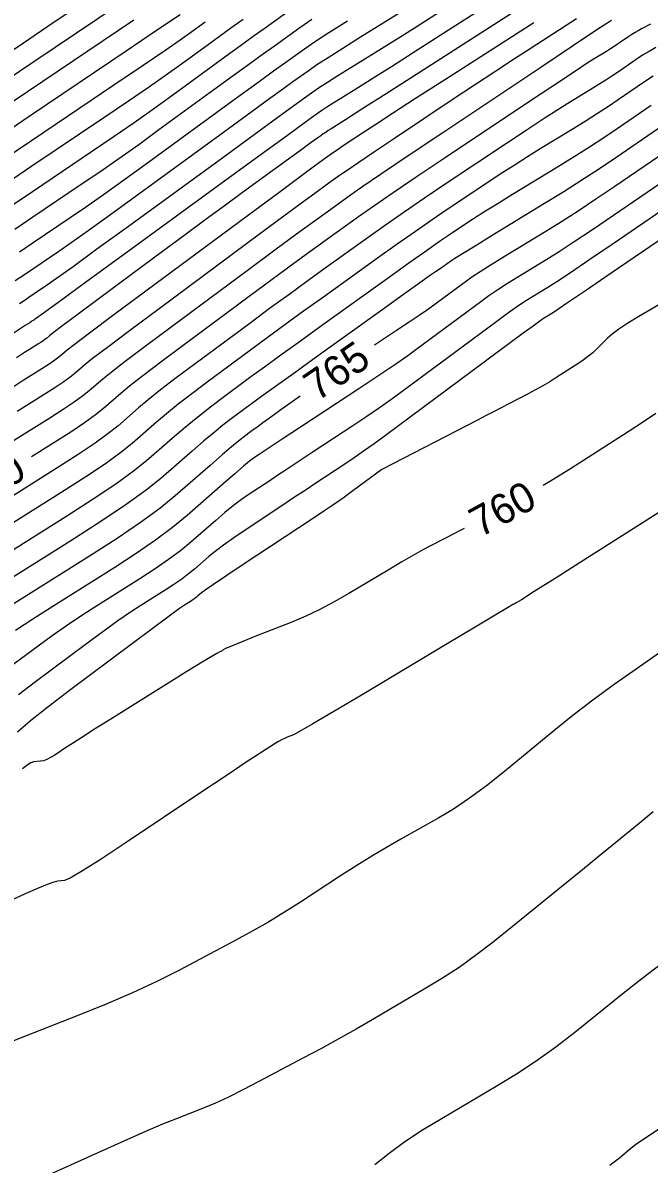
# Model space of a CAD drawing. Extents: x 2079879 to 2092887, y 778083 to 784051.
# Drawn here: x 2084585.7 to 2084644.1, y 781146.9 to 781253.2 of the extents above; entities that cross this region are included whole.
import ezdxf

# ---------------------------------------------------------------- set-up
doc = ezdxf.new("R2010")
doc.units = 0
doc.layers.add('DT_X_Contour_Major', color=7, linetype='Continuous')
doc.layers.add('DT_X_Contour_Minor', color=7, linetype='Continuous')

msp = doc.modelspace()

# ---------------------------------------------------------------- linework, layer by layer
at = {"layer": 'DT_X_Contour_Major'}
for points in [[(2084632, 781256.8), (2084624.61, 781252.06), (2084622.09, 781250.45), (2084620.06, 781249.15), (2084618.52, 781248.17), (2084617.48, 781247.52), (2084615.35, 781246.2), (2084614.62, 781245.75), (2084614.03, 781245.37), (2084613.57, 781245.08), (2084613.25, 781244.86), (2084612.59, 781244.39), (2084611.91, 781243.89), (2084610.35, 781242.75), (2084607.91, 781240.98), (2084604.6, 781238.56), (2084594.6, 781231.28), (2084591.31, 781228.88), (2084588.94, 781227.15), (2084587.49, 781226.1), (2084586.96, 781225.71), (2084586.77, 781225.59), (2084586.7, 781225.54), (2084586.64, 781225.5), (2084586.57, 781225.45), (2084586.51, 781225.41), (2084586.34, 781225.29), (2084585.92, 781225.02), (2084584.8, 781224.27)], [(2084594.67, 781254.96), (2084586.71, 781249.59), (2084584.05, 781247.8), (2084582.03, 781246.44), (2084580.66, 781245.51), (2084579.93, 781245.02), (2084578.85, 781244.3), (2084578.48, 781244.04), (2084578.16, 781243.83), (2084577.89, 781243.65), (2084577.68, 781243.5), (2084577.2, 781243.17), (2084576.64, 781242.79), (2084575.32, 781241.88), (2084573.25, 781240.45), (2084570.42, 781238.5), (2084561.86, 781232.61), (2084561.21, 781232.17)], [(2084611.07, 781254.75), (2084608.27, 781252.74), (2084607.17, 781251.95), (2084605.97, 781251.08), (2084604.66, 781250.13), (2084603.24, 781249.1), (2084599.33, 781246.24), (2084597.78, 781245.13), (2084596.07, 781243.93), (2084594.21, 781242.64), (2084592.19, 781241.27), (2084586.58, 781237.49), (2084584.51, 781236.09), (2084582.5, 781234.72), (2084580.56, 781233.39), (2084578.67, 781232.1), (2084573.73, 781228.7), (2084571.94, 781227.46), (2084570.26, 781226.32), (2084568.69, 781225.27), (2084568.44, 781225.1)], [(2084644.2, 781253.11), (2084643.37, 781252.67), (2084643.07, 781252.5), (2084642.77, 781252.33), (2084642.47, 781252.14), (2084642.18, 781251.95), (2084641.42, 781251.43), (2084641.13, 781251.24), (2084640.81, 781251.03), (2084640.47, 781250.81), (2084640.1, 781250.58), (2084639.1, 781249.97), (2084638.41, 781249.53), (2084637.11, 781248.68), (2084635.19, 781247.41), (2084632.66, 781245.72), (2084625.08, 781240.67), (2084622.44, 781238.9), (2084620.21, 781237.4), (2084618.4, 781236.15), (2084616.99, 781235.16), (2084613.79, 781232.86), (2084612.45, 781231.89), (2084610.84, 781230.72), (2084608.95, 781229.32), (2084606.78, 781227.72), (2084600.63, 781223.17), (2084598.54, 781221.61), (2084596.87, 781220.34), (2084595.63, 781219.37), (2084594.82, 781218.7), (2084593.21, 781217.3), (2084592.47, 781216.7), (2084591.45, 781215.97), (2084590.15, 781215.1), (2084588.57, 781214.09), (2084586.49, 781212.78)], [(2084645.66, 781241.25), (2084640.87, 781237.98), (2084639.12, 781236.79), (2084637.46, 781235.7), (2084635.9, 781234.7), (2084634.44, 781233.79), (2084630.65, 781231.48), (2084629.36, 781230.68), (2084628.33, 781230.03), (2084627.56, 781229.53), (2084627.04, 781229.17), (2084623.76, 781226.73), (2084623.32, 781226.42), (2084622.64, 781225.96), (2084621.71, 781225.34), (2084620.54, 781224.56), (2084618.47, 781223.19)], [(2084611.54, 781218.44), (2084609.75, 781217.16), (2084608.82, 781216.49), (2084608.07, 781215.95), (2084607.49, 781215.53), (2084607.08, 781215.23), (2084606.23, 781214.6), (2084605.8, 781214.26), (2084605.15, 781213.71), (2084604.26, 781212.96), (2084603.15, 781211.99), (2084599.88, 781209.14), (2084598.46, 781207.98), (2084596.66, 781206.66), (2084594.47, 781205.18), (2084591.9, 781203.53), (2084584.53, 781198.9)], [(2084644.7, 781216.84), (2084643.37, 781215.92), (2084641.68, 781214.83), (2084636.74, 781211.68), (2084634.99, 781210.58), (2084634.21, 781210.11)], [(2084626.83, 781206.1), (2084626.53, 781205.95), (2084625.8, 781205.57), (2084625.17, 781205.25), (2084623.65, 781204.47), (2084622.98, 781204.11), (2084622.11, 781203.62), (2084621.04, 781203), (2084619.76, 781202.24), (2084616.09, 781200.05), (2084614.73, 781199.27), (2084613.39, 781198.56), (2084612.07, 781197.94), (2084610.77, 781197.39), (2084607.33, 781196.03), (2084606.19, 781195.58), (2084605.35, 781195.24), (2084604.82, 781195.02), (2084604.59, 781194.92), (2084604.38, 781194.79), (2084604.26, 781194.72), (2084604.06, 781194.61), (2084603.79, 781194.45), (2084602.4, 781193.64), (2084601.85, 781193.31), (2084600.98, 781192.78), (2084599.8, 781192.05), (2084598.3, 781191.11), (2084593.88, 781188.34), (2084592.38, 781187.4), (2084591.19, 781186.64), (2084590.32, 781186.08), (2084589.75, 781185.72), (2084588.66, 781184.99), (2084588.27, 781184.75), (2084587.92, 781184.57), (2084587.62, 781184.46), (2084587.35, 781184.41), (2084586.69, 781184.37), (2084586.42, 781184.28), (2084586.08, 781184.06), (2084585.67, 781183.7)], [(2084661.61, 781160.96), (2084659.04, 781159.23), (2084656.15, 781157.33), (2084648.5, 781152.39), (2084645.96, 781150.74), (2084644.06, 781149.49), (2084642.81, 781148.65), (2084642.22, 781148.21), (2084641.49, 781147.59), (2084641.19, 781147.34), (2084640.83, 781147.05), (2084640.42, 781146.73)]]:
    msp.add_lwpolyline(points, dxfattribs=at)
at = {"layer": 'DT_X_Contour_Minor'}
for points in [[(2084594.68, 781257.37), (2084588.03, 781252.89), (2084585.74, 781251.34), (2084583.84, 781250.06)], [(2084622.06, 781254.92), (2084617.18, 781251.9), (2084615.51, 781250.85), (2084614.15, 781249.99), (2084613.11, 781249.31), (2084612.38, 781248.81), (2084610.87, 781247.73), (2084610.01, 781247.11), (2084608.6, 781246.08), (2084606.61, 781244.64), (2084604.06, 781242.78), (2084596.49, 781237.26), (2084593.9, 781235.38), (2084591.79, 781233.86), (2084590.18, 781232.72), (2084589.05, 781231.94), (2084586.7, 781230.35), (2084585.83, 781229.76), (2084584.98, 781229.19)], [(2084631.69, 781254.4), (2084622.58, 781248.55), (2084619.56, 781246.62), (2084617.31, 781245.18), (2084615.86, 781244.25), (2084615.18, 781243.82), (2084614.43, 781243.36), (2084614.17, 781243.2), (2084613.96, 781243.06), (2084613.8, 781242.96), (2084613.69, 781242.88), (2084613.46, 781242.72), (2084613.19, 781242.52), (2084612.57, 781242.07), (2084611.58, 781241.35), (2084610.24, 781240.37), (2084606.18, 781237.41), (2084604.57, 781236.23), (2084602.79, 781234.93), (2084600.83, 781233.48), (2084598.7, 781231.91), (2084592.79, 781227.53), (2084590.84, 781226.08), (2084589.42, 781225.02), (2084588.52, 781224.35), (2084588.16, 781224.07), (2084587.88, 781223.83), (2084587.75, 781223.72), (2084587.58, 781223.6), (2084587.36, 781223.45), (2084587.09, 781223.28), (2084586.3, 781222.78), (2084585.85, 781222.5), (2084585.09, 781222.01)], [(2084624.63, 781254.28), (2084622.81, 781253.12), (2084621.19, 781252.1), (2084619.77, 781251.22), (2084616.26, 781249.05), (2084615.06, 781248.3), (2084614.09, 781247.68), (2084613.34, 781247.2), (2084612.82, 781246.84), (2084611.73, 781246.06), (2084610.96, 781245.5), (2084609.47, 781244.42), (2084607.26, 781242.81), (2084604.33, 781240.67), (2084595.54, 781234.27), (2084592.6, 781232.13), (2084590.37, 781230.51), (2084588.83, 781229.41), (2084588, 781228.82), (2084586.73, 781227.97), (2084586.26, 781227.65), (2084585.81, 781227.34), (2084585.37, 781227.04)], [(2084600.35, 781253.99), (2084598.24, 781252.57), (2084595.32, 781250.6), (2084586.47, 781244.63), (2084583.2, 781242.42)], [(2084602.7, 781253.31), (2084601.22, 781252.23), (2084600.37, 781251.63), (2084598.93, 781250.64), (2084596.9, 781249.26), (2084594.28, 781247.49), (2084586.51, 781242.25), (2084583.64, 781240.31)], [(2084606.23, 781253.56), (2084605.09, 781252.74), (2084604.01, 781251.96), (2084602.97, 781251.2), (2084600.27, 781249.24), (2084599.07, 781248.38), (2084597.5, 781247.28), (2084595.55, 781245.95), (2084593.23, 781244.38), (2084586.54, 781239.87), (2084584.07, 781238.2)], [(2084596.05, 781253.49), (2084586.12, 781246.8), (2084584.15, 781245.47)], [(2084640.57, 781253.47), (2084639.21, 781252.57), (2084637.02, 781251.11), (2084633.98, 781249.08), (2084624.74, 781242.92), (2084621.6, 781240.83), (2084619.12, 781239.15), (2084617.29, 781237.91), (2084616.11, 781237.08), (2084613.83, 781235.45), (2084612.75, 781234.66), (2084611.2, 781233.53), (2084609.19, 781232.05), (2084606.72, 781230.22), (2084599.51, 781224.88), (2084597.09, 781223.08), (2084595.22, 781221.67), (2084593.91, 781220.66), (2084593.15, 781220.04), (2084591.88, 781218.93), (2084591.29, 781218.46), (2084590.48, 781217.88), (2084589.45, 781217.19), (2084588.2, 781216.39), (2084584.57, 781214.11)], [(2084633.33, 781253.25), (2084625.1, 781247.97), (2084622.31, 781246.18), (2084620.14, 781244.78), (2084618.59, 781243.77), (2084617.64, 781243.15), (2084615.93, 781242.01), (2084615.35, 781241.62), (2084614.89, 781241.31), (2084614.55, 781241.08), (2084614.33, 781240.93), (2084613.91, 781240.63), (2084613.34, 781240.21), (2084611.93, 781239.16), (2084609.68, 781237.5), (2084606.6, 781235.22), (2084597.27, 781228.31), (2084594.18, 781226.01), (2084591.91, 781224.32), (2084590.46, 781223.22), (2084589.82, 781222.72), (2084589.21, 781222.19), (2084588.93, 781221.97), (2084588.55, 781221.69), (2084588.05, 781221.36), (2084587.46, 781220.98), (2084585.72, 781219.89), (2084584.87, 781219.35)], [(2084612.64, 781253.55), (2084611.51, 781252.77), (2084609.14, 781251.07), (2084608.12, 781250.34), (2084606.84, 781249.41), (2084605.31, 781248.3), (2084603.51, 781246.99), (2084598.38, 781243.25), (2084596.49, 781241.88), (2084594.65, 781240.57), (2084592.87, 781239.33), (2084591.14, 781238.16), (2084586.62, 781235.11), (2084584.95, 781233.98)], [(2084637.32, 781253.6), (2084633.09, 781250.89), (2084631.44, 781249.82), (2084629.68, 781248.68), (2084627.8, 781247.44), (2084625.81, 781246.11), (2084620.33, 781242.47), (2084618.48, 781241.22), (2084617, 781240.23), (2084615.92, 781239.49), (2084615.22, 781239.01), (2084613.87, 781238.04), (2084613.04, 781237.43), (2084611.56, 781236.35), (2084609.44, 781234.78), (2084606.66, 781232.72), (2084598.39, 781226.59), (2084595.64, 781224.54), (2084593.57, 781222.99), (2084592.18, 781221.94), (2084591.49, 781221.38), (2084590.55, 781220.56), (2084590.11, 781220.21), (2084589.51, 781219.78), (2084588.75, 781219.27), (2084587.83, 781218.68), (2084585.15, 781217)], [(2084615.95, 781253.4), (2084614.21, 781252.3), (2084612.87, 781251.43), (2084611.94, 781250.79), (2084610, 781249.4), (2084609.07, 781248.72), (2084607.72, 781247.75), (2084605.96, 781246.47), (2084603.78, 781244.88), (2084597.44, 781240.26), (2084595.19, 781238.63), (2084593.22, 781237.22), (2084591.52, 781236.02), (2084590.1, 781235.05), (2084586.66, 781232.73), (2084585.39, 781231.87)], [(2084644.7, 781250.95), (2084644.08, 781250.58), (2084643.47, 781250.21), (2084642.88, 781249.81), (2084641.31, 781248.74), (2084640.7, 781248.33), (2084640.04, 781247.9), (2084639.34, 781247.46), (2084638.59, 781246.99), (2084636.51, 781245.73), (2084635.57, 781245.14), (2084634.3, 781244.31), (2084632.7, 781243.26), (2084630.77, 781241.98), (2084625.17, 781238.25), (2084623.14, 781236.89), (2084621.25, 781235.6), (2084619.5, 781234.38), (2084617.88, 781233.23), (2084613.75, 781230.27), (2084612.16, 781229.12), (2084610.48, 781227.9), (2084608.7, 781226.6), (2084606.84, 781225.22), (2084601.75, 781221.45), (2084599.99, 781220.14), (2084598.53, 781219.02), (2084597.36, 781218.09), (2084596.48, 781217.36), (2084594.55, 781215.66), (2084593.65, 781214.95), (2084592.42, 781214.06), (2084590.85, 781213.01), (2084588.94, 781211.79), (2084583.42, 781208.32)], [(2084644.47, 781248.27), (2084643.57, 781247.67), (2084641.2, 781246.05), (2084640.28, 781245.43), (2084639.28, 781244.78), (2084638.21, 781244.1), (2084637.07, 781243.4), (2084633.93, 781241.48), (2084632.73, 781240.74), (2084631.49, 781239.95), (2084630.2, 781239.12), (2084628.87, 781238.24), (2084625.26, 781235.83), (2084623.84, 781234.87), (2084622.29, 781233.8), (2084620.59, 781232.61), (2084618.77, 781231.31), (2084613.71, 781227.68), (2084611.86, 781226.35), (2084610.11, 781225.08), (2084608.46, 781223.87), (2084606.9, 781222.72), (2084602.87, 781219.74), (2084601.45, 781218.67), (2084600.18, 781217.69), (2084599.08, 781216.81), (2084598.15, 781216.02), (2084595.88, 781214.03), (2084594.83, 781213.19), (2084593.39, 781212.15), (2084591.55, 781210.92), (2084589.32, 781209.5), (2084582.84, 781205.43)], [(2084644.27, 781245.53), (2084641.09, 781243.36), (2084639.85, 781242.53), (2084638.51, 781241.66), (2084637.08, 781240.75), (2084635.55, 781239.8), (2084631.35, 781237.24), (2084629.9, 781236.34), (2084628.68, 781235.59), (2084627.71, 781234.97), (2084626.98, 781234.5), (2084625.36, 781233.42), (2084624.54, 781232.86), (2084623.32, 781232), (2084621.69, 781230.84), (2084619.65, 781229.39), (2084613.67, 781225.09), (2084611.57, 781223.58), (2084609.75, 781222.27), (2084608.21, 781221.15), (2084606.96, 781220.23), (2084603.99, 781218.03), (2084602.9, 781217.2), (2084601.84, 781216.37), (2084600.81, 781215.52), (2084599.82, 781214.67), (2084597.21, 781212.4), (2084596.01, 781211.44), (2084594.35, 781210.25), (2084592.25, 781208.83), (2084589.69, 781207.2), (2084582.26, 781202.54)], [(2084644.96, 781243.39), (2084640.98, 781240.67), (2084639.44, 781239.64), (2084637.82, 781238.58), (2084636.12, 781237.5), (2084634.33, 781236.39), (2084629.46, 781233.41), (2084627.85, 781232.43), (2084626.68, 781231.71), (2084625.96, 781231.27), (2084625.68, 781231.09), (2084625.17, 781230.71), (2084625.11, 781230.67), (2084625, 781230.59), (2084624.86, 781230.5), (2084624.68, 781230.38), (2084624.15, 781230.03), (2084623.69, 781229.71), (2084622.7, 781229.01), (2084621.19, 781227.93), (2084619.16, 781226.47), (2084613.04, 781222.08), (2084610.94, 781220.57), (2084609.24, 781219.35), (2084607.93, 781218.4), (2084607.02, 781217.73), (2084605.11, 781216.32), (2084604.35, 781215.73), (2084603.49, 781215.04), (2084602.53, 781214.24), (2084601.48, 781213.33), (2084598.54, 781210.77), (2084597.19, 781209.68), (2084595.32, 781208.34), (2084592.95, 781206.75), (2084590.06, 781204.9), (2084581.69, 781199.64)], [(2084646.35, 781239.11), (2084640.75, 781235.28), (2084638.79, 781233.95), (2084637.1, 781232.83), (2084635.69, 781231.9), (2084634.54, 781231.18), (2084631.85, 781229.54), (2084630.88, 781228.93), (2084629.98, 781228.35), (2084629.15, 781227.79), (2084628.4, 781227.24), (2084622.34, 781222.75), (2084621.57, 781222.21), (2084620.45, 781221.44), (2084618.96, 781220.43), (2084617.1, 781219.2), (2084611.68, 781215.62), (2084609.88, 781214.43), (2084608.57, 781213.56), (2084607.73, 781213.01), (2084607.38, 781212.78), (2084607.07, 781212.57), (2084606.82, 781212.37), (2084606.27, 781211.91), (2084605.45, 781211.2), (2084604.34, 781210.24), (2084601.01, 781207.33), (2084599.65, 781206.21), (2084598.07, 781205.02), (2084596.27, 781203.78), (2084594.26, 781202.47), (2084588.59, 781198.91), (2084586.62, 781197.67), (2084584.99, 781196.61)], [(2084647.04, 781236.96), (2084640.64, 781232.59), (2084638.47, 781231.11), (2084636.74, 781229.95), (2084635.47, 781229.11), (2084634.64, 781228.58), (2084633.05, 781227.6), (2084632.39, 781227.19), (2084631.62, 781226.67), (2084630.74, 781226.04), (2084629.75, 781225.32), (2084620.92, 781218.77), (2084620, 781218.11), (2084618.95, 781217.37), (2084617.77, 781216.56), (2084616.45, 781215.68), (2084612.75, 781213.24), (2084611.45, 781212.38), (2084610.33, 781211.64), (2084609.38, 781211.01), (2084608.61, 781210.5), (2084606.79, 781209.3), (2084606.09, 781208.81), (2084605.33, 781208.24), (2084604.53, 781207.59), (2084603.68, 781206.86), (2084601.34, 781204.82), (2084600.39, 781204.04), (2084599.28, 781203.21), (2084598.03, 781202.34), (2084596.61, 781201.42), (2084592.64, 781198.93), (2084591.18, 781197.99), (2084589.77, 781197.05), (2084588.41, 781196.11), (2084587.11, 781195.15), (2084583.71, 781192.62)], [(2084647.74, 781234.82), (2084640.53, 781229.9), (2084638.14, 781228.27), (2084636.38, 781227.07), (2084635.25, 781226.31), (2084634.75, 781225.98), (2084634.24, 781225.67), (2084633.9, 781225.44), (2084633.27, 781224.98), (2084632.34, 781224.3), (2084631.11, 781223.4), (2084619.5, 781214.79), (2084618.43, 781214.01), (2084617.46, 781213.31), (2084616.58, 781212.7), (2084615.79, 781212.17), (2084613.82, 781210.86), (2084613.02, 781210.33), (2084612.09, 781209.72), (2084611.03, 781209.02), (2084609.84, 781208.23), (2084606.52, 781206.02), (2084605.36, 781205.24), (2084604.39, 781204.56), (2084603.61, 781203.97), (2084603.02, 781203.49), (2084601.68, 781202.32), (2084601.13, 781201.87), (2084600.5, 781201.4), (2084599.78, 781200.9), (2084598.97, 781200.37), (2084596.69, 781198.94), (2084595.73, 781198.31), (2084594.55, 781197.49), (2084593.14, 781196.48), (2084591.51, 781195.27), (2084586.87, 781191.81), (2084585.29, 781190.6)], [(2084646.09, 781227.61), (2084643.12, 781225.86), (2084642.1, 781225.24), (2084641.27, 781224.7), (2084640.62, 781224.23), (2084640.17, 781223.82), (2084639.22, 781222.85), (2084638.82, 781222.48), (2084638.35, 781222.1), (2084637.81, 781221.7), (2084637.2, 781221.3), (2084635.47, 781220.2), (2084634.82, 781219.79), (2084634.16, 781219.4), (2084633.49, 781219.03), (2084632.81, 781218.66), (2084631, 781217.72), (2084630.3, 781217.36), (2084629.58, 781216.99), (2084628.84, 781216.61), (2084628.08, 781216.21), (2084619.15, 781211.61), (2084616.47, 781209.62), (2084615.95, 781209.24), (2084615.56, 781208.95), (2084615.29, 781208.75), (2084615.14, 781208.65), (2084614.89, 781208.49), (2084614.59, 781208.28), (2084613.85, 781207.79), (2084612.68, 781207.02), (2084606.24, 781202.74), (2084604.63, 781201.68), (2084603.45, 781200.88), (2084602.69, 781200.36), (2084602.35, 781200.11), (2084602.01, 781199.82), (2084601.87, 781199.7), (2084601.71, 781199.58), (2084601.53, 781199.46), (2084601.33, 781199.32), (2084600.75, 781198.96), (2084600.28, 781198.64), (2084599.32, 781197.93), (2084597.86, 781196.85), (2084595.91, 781195.39), (2084590.03, 781191), (2084588.02, 781189.47), (2084586.41, 781188.18), (2084585.2, 781187.12)], [(2084646.16, 781208.36), (2084638, 781203.16), (2084635.31, 781201.46), (2084633.37, 781200.23), (2084632.18, 781199.47), (2084631.75, 781199.2), (2084631.58, 781199.11), (2084631.51, 781199.08), (2084631.46, 781199.05), (2084631.41, 781199.03), (2084631.37, 781199.01), (2084631.28, 781198.96), (2084630.87, 781198.72), (2084629.74, 781198.04), (2084627.86, 781196.92), (2084625.25, 781195.36), (2084617.32, 781190.62), (2084614.69, 781189.05), (2084612.74, 781187.91), (2084611.49, 781187.18), (2084610.92, 781186.88), (2084610.32, 781186.65), (2084610.09, 781186.55), (2084609.82, 781186.41), (2084609.53, 781186.25), (2084609.22, 781186.06), (2084608.34, 781185.51), (2084607.72, 781185.11), (2084606.52, 781184.32), (2084604.75, 781183.13), (2084602.39, 781181.56), (2084595.33, 781176.85), (2084592.99, 781175.3), (2084591.25, 781174.19), (2084590.11, 781173.52), (2084589.57, 781173.29), (2084588.94, 781173.25), (2084588.57, 781173.16), (2084587.95, 781172.93), (2084587.06, 781172.56), (2084585.92, 781172.05), (2084582.52, 781170.49)], [(2084648.47, 781196.91), (2084642.86, 781193.01), (2084640.81, 781191.56), (2084638.84, 781190.11), (2084636.97, 781188.68), (2084635.2, 781187.25), (2084630.59, 781183.46), (2084628.91, 781182.13), (2084627.33, 781180.96), (2084625.85, 781179.96), (2084624.47, 781179.13), (2084620.93, 781177.15), (2084619.59, 781176.38), (2084618.22, 781175.56), (2084616.83, 781174.7), (2084615.41, 781173.79), (2084611.58, 781171.28), (2084610.1, 781170.34), (2084608.52, 781169.4), (2084606.85, 781168.44), (2084605.08, 781167.48), (2084600.22, 781164.91), (2084598.23, 781163.91), (2084595.9, 781162.84), (2084593.23, 781161.69), (2084590.21, 781160.48), (2084581.71, 781157.15)], [(2084644.47, 781179.71), (2084643.14, 781178.62), (2084639.31, 781175.47), (2084637.86, 781174.29), (2084636.41, 781173.11), (2084634.95, 781171.92), (2084633.47, 781170.73), (2084629.53, 781167.56), (2084628.02, 781166.4), (2084626.45, 781165.27), (2084624.81, 781164.19), (2084623.1, 781163.16), (2084618.47, 781160.45), (2084616.76, 781159.46), (2084615.09, 781158.52), (2084613.46, 781157.62), (2084611.87, 781156.77), (2084607.7, 781154.56), (2084606.21, 781153.78), (2084604.85, 781153.12), (2084603.64, 781152.56), (2084602.58, 781152.12), (2084599.91, 781151.07), (2084598.71, 781150.58), (2084597.11, 781149.9), (2084595.1, 781149.01), (2084592.69, 781147.93), (2084585.72, 781144.79)], [(2084645.1, 781165.43), (2084643.52, 781164.24), (2084641.83, 781162.9), (2084637.15, 781159.14), (2084635.37, 781157.76), (2084633.56, 781156.46), (2084631.72, 781155.24), (2084629.83, 781154.09), (2084624.77, 781151.13), (2084622.95, 781150.03), (2084621.3, 781148.94), (2084619.83, 781147.86), (2084618.52, 781146.8)]]:
    msp.add_lwpolyline(points, dxfattribs=at)

# ---------------------------------------------------------------- texts
at = {"layer": 'DT_X_Contour_Major'}
for s, rotation, p in [('765', 34.4122, (2084613.14, 781217.9)), ('770', 32.3107, (2084580.93, 781207.62)), ('760', 28.502, (2084628.32, 781205.23))]:
    msp.add_text(s, height=2.8, rotation=rotation, dxfattribs=at).set_placement(p)

doc.saveas('drawing.dxf')
